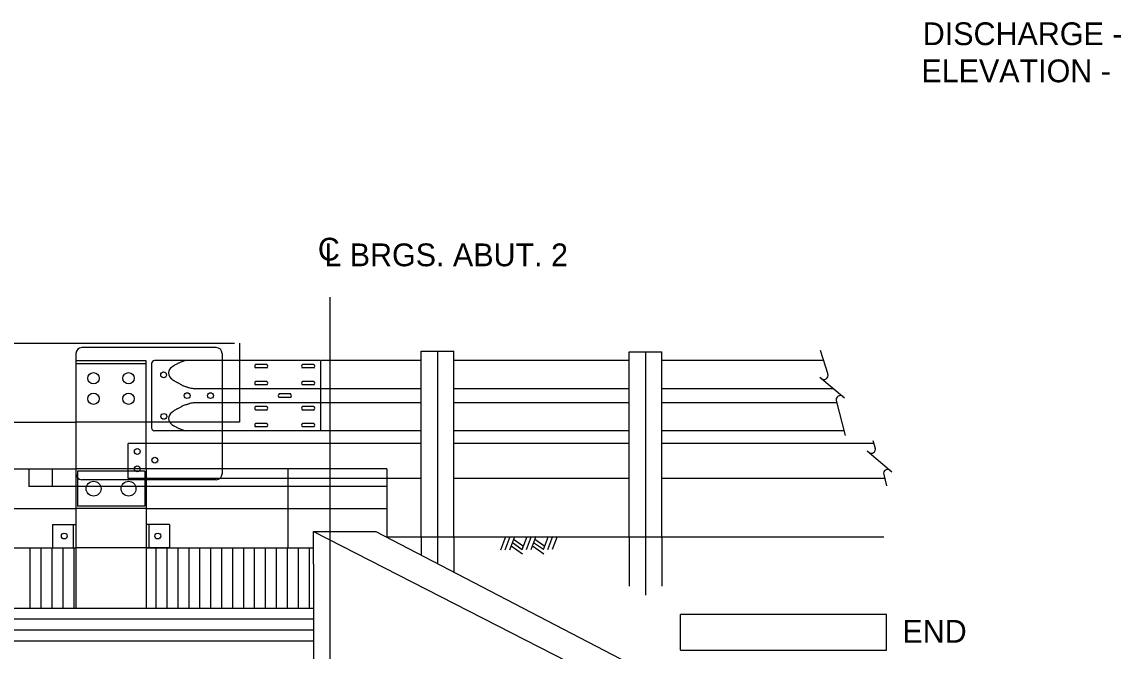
# Model space of a CAD drawing. Extents: x 638263 to 640391, y 293683 to 298655.
# Drawn here: x 638728.4 to 638873.2, y 297468.7 to 297551.6 of the extents above; entities that cross this region are included whole.
import ezdxf

# ---------------------------------------------------------------- set-up
doc = ezdxf.new("R2010")
doc.units = 0
for name, color, linetype in [('2', 7, 'Continuous'), ('3', 7, 'Continuous'), ('4', 7, 'Continuous'), ('5', 7, 'Continuous'), ('Level 25', 7, 'Continuous')]:
    doc.layers.add(name, color=color, linetype=linetype)

msp = doc.modelspace()

# ---------------------------------------------------------------- linework, layer by layer
at = {"layer": '2'}
for p, q in [((638583.44, 297509.28), (638756.44, 297509.28)), ((638757.09, 297509.28), (638757.09, 297506.97)), ((638744.78, 297506.96), (638735.54, 297506.96)), ((638735.54, 297506.96), (638735.54, 297492.72)), ((638744.78, 297506.58), (638735.54, 297506.58)), ((638744.78, 297492.72), (638744.78, 297506.96)), ((638745.51, 297506.61), (638745.51, 297498.11)), ((638757.09, 297506.98), (638745.88, 297506.98)), ((638767.68, 297506.98), (638757.09, 297506.98)), ((638757.09, 297506.96), (638757.09, 297498.88)), ((638767.75, 297506.98), (638767.75, 297497.74)), ((638781.02, 297506.98), (638767.75, 297506.98)), ((638808.42, 297506.98), (638785.35, 297506.98)), ((638834.04, 297506.98), (638812.74, 297506.98)), ((638760.7, 297506.47), (638759.22, 297506.47)), ((638760.7, 297506.01), (638759.22, 297506.01)), ((638766.88, 297506.47), (638765.4, 297506.47)), ((638766.88, 297506.01), (638765.4, 297506.01)), ((638760.7, 297504.25), (638759.22, 297504.25)), ((638760.7, 297503.79), (638759.22, 297503.79)), ((638766.88, 297504.25), (638765.4, 297504.25)), ((638766.88, 297503.79), (638765.4, 297503.79)), ((638757.09, 297503.28), (638751.34, 297503.28)), ((638781.02, 297503.28), (638757.09, 297503.28)), ((638763.79, 297502.59), (638762.32, 297502.59)), ((638808.42, 297503.28), (638785.35, 297503.28)), ((638835.36, 297503.28), (638812.74, 297503.28)), ((638757.09, 297501.43), (638751.34, 297501.43)), ((638781.02, 297501.43), (638757.09, 297501.43)), ((638760.7, 297500.93), (638759.22, 297500.93)), ((638763.79, 297502.13), (638762.32, 297502.13)), ((638766.88, 297500.93), (638765.4, 297500.93)), ((638808.42, 297501.43), (638785.35, 297501.43)), ((638835.8, 297501.43), (638812.74, 297501.43)), ((638760.7, 297500.46), (638759.22, 297500.46)), ((638766.88, 297500.46), (638765.4, 297500.46)), ((638695.15, 297498.88), (638735.54, 297498.88)), ((638744.78, 297498.88), (638735.54, 297498.88)), ((638754.78, 297498.88), (638744.78, 297498.88)), ((638757.09, 297498.88), (638754.78, 297498.88)), ((638760.7, 297498.71), (638759.22, 297498.71)), ((638760.7, 297498.25), (638759.22, 297498.25)), ((638766.88, 297498.71), (638765.4, 297498.71)), ((638766.88, 297498.25), (638765.4, 297498.25)), ((638754.79, 297497.74), (638745.88, 297497.74)), ((638781.02, 297497.74), (638754.79, 297497.74)), ((638808.42, 297497.74), (638785.35, 297497.74)), ((638836.72, 297497.74), (638812.74, 297497.74)), ((638742.43, 297491.46), (638742.43, 297496.08)), ((638754.79, 297496.08), (638742.43, 297496.08)), ((638781.02, 297496.08), (638754.79, 297496.08)), ((638808.42, 297496.08), (638785.35, 297496.08)), ((638840.66, 297496.08), (638812.74, 297496.08)), ((638695.15, 297492.72), (638735.54, 297492.72)), ((638729.37, 297490.41), (638729.37, 297492.72)), ((638732.46, 297490.41), (638732.46, 297492.72)), ((638744.78, 297492.72), (638735.54, 297492.72)), ((638735.54, 297492.72), (638735.54, 297474.4)), ((638744.61, 297492.44), (638735.73, 297492.44)), ((638735.73, 297492.44), (638735.73, 297487.82)), ((638744.61, 297492.44), (638744.61, 297487.82)), ((638776.52, 297492.72), (638744.78, 297492.72)), ((638744.78, 297492.72), (638744.78, 297474.4)), ((638754.79, 297492.72), (638754.79, 297492.06)), ((638776.51, 297491.46), (638742.41, 297491.46)), ((638781.02, 297491.46), (638776.52, 297491.46)), ((638808.42, 297491.46), (638785.35, 297491.46)), ((638842.1, 297491.46), (638812.74, 297491.46)), ((638776.51, 297490.41), (638729.35, 297490.41)), ((638744.61, 297487.82), (638735.73, 297487.82)), ((638695.15, 297487.52), (638735.54, 297487.52)), ((638744.78, 297487.52), (638735.54, 297487.52)), ((638732.45, 297485.42), (638735.54, 297485.42)), ((638732.45, 297485.42), (638732.45, 297482.33)), ((638735.18, 297485.42), (638735.18, 297482.33)), ((638735.54, 297485.42), (638735.54, 297482.33)), ((638747.87, 297485.42), (638744.78, 297485.42)), ((638744.78, 297485.42), (638744.78, 297482.33)), ((638745.14, 297485.42), (638745.14, 297482.33)), ((638747.87, 297485.42), (638747.87, 297482.33)), ((638732.45, 297482.33), (638735.54, 297482.33)), ((638744.78, 297482.33), (638735.54, 297482.33)), ((638747.87, 297482.33), (638744.78, 297482.33))]:
    msp.add_line(p, q, dxfattribs=at)
for centre, radius in [((638737.85, 297504.66), 0.748), ((638742.47, 297504.66), 0.748), ((638747.09, 297505.1), 0.385), ((638737.85, 297501.96), 0.748), ((638742.47, 297501.96), 0.748), ((638750.19, 297502.37), 0.385), ((638753.27, 297502.37), 0.385), ((638747.12, 297499.64), 0.385), ((638743.62, 297495.02), 0.385), ((638745.93, 297493.87), 0.385), ((638743.62, 297492.72), 0.385), ((638737.86, 297490.12), 0.978), ((638742.47, 297490.12), 0.978), ((638734, 297483.88), 0.385), ((638746.32, 297483.88), 0.385)]:
    msp.add_circle(centre, radius, dxfattribs=at)
for centre, radius, start, end in [((638745.88, 297506.61), 0.369, 90, 180), ((638763.15, 297478.14), 31.8, 116.5749, 117.3798), ((638750.01, 297504.42), 2.42, 113.6547, 116.5749), ((638751.42, 297501.2), 5.93, 112.3149, 113.6547), ((638773.74, 297446.81), 64.73, 111.9093, 112.3149), ((638750.29, 297505.11), 1.88, 108.4934, 111.9093), ((638752.92, 297497.25), 10.17, 107.0234, 108.4934), ((638748.65, 297505.35), 0.916, 120.3532, 238.6149), ((638750.97, 297502.7), 4.42, 125.3229, 129.0151), ((638748.97, 297505.53), 0.955, 117.3798, 125.3229), ((638759.36, 297506.24), 0.269, 120.8559, 239.1441), ((638760.56, 297506.24), 0.269, 300.8559, 59.1441), ((638765.54, 297506.24), 0.269, 120.8559, 239.1441), ((638766.74, 297506.24), 0.269, 300.8559, 59.1441), ((638751.4, 297508.3), 4.94, 229.2007, 233.1182), ((638749.09, 297505.22), 1.09, 233.1182, 241.475), ((638936.16, 297849.41), 392.83, 241.475, 241.5275), ((638688.64, 297393.02), 126.36, 61.435, 61.5275), ((638694.04, 297402.92), 115.08, 61.2499, 61.435), ((638759.71, 297522.63), 21.45, 241.2499, 241.6785), ((638749.84, 297504.31), 0.644, 241.6785, 249.7671), ((638755.9, 297520.76), 18.18, 249.7671, 251.2889), ((638759.36, 297504.02), 0.269, 120.8559, 239.1441), ((638760.56, 297504.02), 0.269, 300.8559, 59.1441), ((638765.54, 297504.02), 0.269, 120.8559, 239.1441), ((638766.74, 297504.02), 0.269, 300.8559, 59.1441), ((638751.08, 297506.52), 3.14, 251.2889, 252.6389), ((638777.58, 297591.29), 91.96, 252.6389, 252.8885), ((638751.16, 297505.47), 2.16, 252.8885, 261.633), ((638751.58, 297508.31), 5.03, 261.633, 267.3571), ((638762.46, 297502.36), 0.269, 120.8559, 239.1441), ((638763.66, 297502.36), 0.269, 300.8559, 59.1441), ((638694.04, 297601.79), 115.08, 298.565, 298.7501), ((638759.71, 297482.09), 21.45, 118.3215, 118.7501), ((638749.84, 297500.41), 0.644, 110.2329, 118.3215), ((638755.9, 297483.96), 18.18, 108.7111, 110.2329), ((638751.08, 297498.19), 3.14, 107.3611, 108.7111), ((638777.58, 297413.42), 91.96, 107.1115, 107.3611), ((638751.16, 297499.25), 2.16, 98.367, 107.1115), ((638751.58, 297496.41), 5.03, 92.6429, 98.367), ((638759.36, 297500.7), 0.269, 120.8559, 239.1441), ((638760.56, 297500.7), 0.269, 300.8559, 59.1441), ((638765.54, 297500.7), 0.269, 120.8559, 239.1441), ((638766.74, 297500.7), 0.269, 300.8559, 59.1441), ((638748.65, 297499.37), 0.916, 121.3851, 239.6468), ((638751.4, 297496.41), 4.94, 126.8818, 130.7993), ((638749.09, 297499.49), 1.09, 118.525, 126.8818), ((638936.16, 297155.3), 392.83, 118.4725, 118.525), ((638688.64, 297611.7), 126.36, 298.4725, 298.565), ((638745.88, 297498.11), 0.369, 180, 270), ((638750.97, 297502.01), 4.42, 230.9849, 234.6771), ((638748.97, 297499.19), 0.955, 234.6771, 242.6202), ((638763.15, 297526.58), 31.8, 242.6202, 243.4251), ((638750.01, 297500.3), 2.42, 243.4251, 246.3453), ((638751.42, 297503.52), 5.93, 246.3453, 247.6851), ((638773.74, 297557.91), 64.73, 247.6851, 248.0907), ((638759.36, 297498.48), 0.269, 120.8559, 239.1441), ((638760.56, 297498.48), 0.269, 300.8559, 59.1441), ((638765.54, 297498.48), 0.269, 120.8559, 239.1441), ((638766.74, 297498.48), 0.269, 300.8559, 59.1441), ((638750.29, 297499.61), 1.88, 248.0907, 251.5066), ((638752.92, 297507.46), 10.17, 251.5066, 252.9766)]:
    msp.add_arc(centre, radius, start, end, dxfattribs=at)
at = {"layer": '3'}
for p, q in [((638781.02, 297508.24), (638785.35, 297508.24)), ((638781.02, 297483.77), (638781.02, 297508.24)), ((638783.18, 297508.24), (638783.18, 297480.27)), ((638785.35, 297483.77), (638785.35, 297508.24)), ((638808.42, 297508.16), (638812.74, 297508.16)), ((638808.42, 297483.77), (638808.42, 297508.16)), ((638810.58, 297508.16), (638810.58, 297476.08)), ((638812.74, 297483.77), (638812.74, 297508.16)), ((638833.6, 297508.34), (638834.61, 297505.19)), ((638833.54, 297504.8), (638836.81, 297502.06)), ((638835.73, 297501.72), (638836.88, 297497.13)), ((638840.53, 297496.46), (638840.85, 297495.47)), ((638839.78, 297495.08), (638843.05, 297492.34)), ((638763.51, 297482.33), (638763.51, 297492.72)), ((638776.52, 297492.72), (638776.52, 297483.77)), ((638841.97, 297492), (638842.34, 297490.49)), ((638744.76, 297487.52), (638776.52, 297487.52)), ((638766.86, 297484.49), (638833.06, 297450.61)), ((638766.86, 297484.49), (638775.07, 297484.49)), ((638766.86, 297480.17), (638766.86, 297484.49)), ((638775.07, 297484.49), (638840.19, 297450.61)), ((638776.45, 297483.77), (638842, 297483.77)), ((638781.02, 297483.77), (638781.02, 297481.4)), ((638785.35, 297483.77), (638785.35, 297479.15)), ((638792.15, 297483.77), (638791.48, 297482.02)), ((638792.69, 297483.78), (638792.03, 297482.02)), ((638793.33, 297483.79), (638792.67, 297482.03)), ((638793.2, 297483.45), (638794.49, 297482.55)), ((638794.96, 297483.79), (638794.3, 297482.06)), ((638795.51, 297483.8), (638794.85, 297482.07)), ((638796.14, 297483.8), (638795.49, 297482.08)), ((638796.01, 297483.46), (638797.3, 297482.56)), ((638797.77, 297483.8), (638797.11, 297482.07)), ((638798.32, 297483.81), (638797.66, 297482.08)), ((638798.95, 297483.81), (638798.3, 297482.09)), ((638808.42, 297483.77), (638808.42, 297477.28)), ((638812.74, 297483.77), (638812.74, 297477.28)), ((638695.15, 297482.33), (638735.54, 297482.33)), ((638744.78, 297482.33), (638766.86, 297482.33)), ((638792.87, 297482.57), (638794.37, 297481.53)), ((638793.04, 297483.02), (638794.33, 297482.12)), ((638795.68, 297482.58), (638797.18, 297481.54)), ((638795.85, 297483.03), (638797.14, 297482.13)), ((638766.86, 297480.17), (638766.86, 297418.67)), ((638574.49, 297474.4), (638766.86, 297474.4))]:
    msp.add_line(p, q, dxfattribs=at)
for centre, start, end in [((638834.11, 297505.03), 227.8504, 17.8504), ((638836.25, 297501.84), 49.9832, 192.5218), ((638836.25, 297501.84), 49.9832, 49.9972), ((638840.35, 297495.31), 227.8504, 17.8504), ((638842.49, 297492.12), 49.9832, 192.5218), ((638842.49, 297492.12), 49.9832, 49.9972)]:
    msp.add_arc(centre, 0.533, start, end, dxfattribs=at)
at = {"layer": '4'}
for p, q in [((638769.01, 297515.36), (638769.01, 297449.75)), ((638842.34, 297473.55), (638815.19, 297473.55)), ((638815.19, 297468.85), (638815.19, 297473.55)), ((638842.34, 297468.85), (638842.34, 297473.55)), ((638815.19, 297468.85), (638842.34, 297468.85))]:
    msp.add_line(p, q, dxfattribs=at)
at = {"layer": '5'}
for p, q in [((638729.48, 297482.33), (638729.48, 297474.4)), ((638730.93, 297482.33), (638730.93, 297474.4)), ((638732.37, 297482.33), (638732.37, 297474.4)), ((638733.82, 297482.33), (638733.82, 297474.4)), ((638735.26, 297482.33), (638735.26, 297474.4)), ((638746.07, 297482.33), (638746.07, 297474.4)), ((638747.51, 297482.33), (638747.51, 297474.4)), ((638748.95, 297482.33), (638748.95, 297474.4)), ((638750.39, 297482.33), (638750.39, 297474.4)), ((638751.83, 297482.33), (638751.83, 297474.4)), ((638753.28, 297482.33), (638753.28, 297474.4)), ((638754.72, 297482.33), (638754.72, 297474.4)), ((638756.16, 297482.33), (638756.16, 297474.4)), ((638757.6, 297482.33), (638757.6, 297474.4)), ((638759.04, 297482.33), (638759.04, 297474.4)), ((638760.48, 297482.33), (638760.48, 297474.4)), ((638761.93, 297482.33), (638761.93, 297474.4)), ((638763.37, 297482.33), (638763.37, 297474.4)), ((638764.81, 297482.33), (638764.81, 297474.4)), ((638766.25, 297482.33), (638766.25, 297474.4)), ((638574.49, 297472.96), (638766.86, 297472.96)), ((638574.49, 297471.52), (638766.86, 297471.52)), ((638574.49, 297470.07), (638766.86, 297470.07))]:
    msp.add_line(p, q, dxfattribs=at)
at = {"layer": 'Level 25'}
for p, q in [((638754.02, 297508.7), (638736.31, 297508.7)), ((638735.54, 297507.93), (638735.54, 297506.96)), ((638754.79, 297507.93), (638754.79, 297506.97)), ((638754.79, 297506.97), (638754.79, 297497.73)), ((638754.79, 297497.73), (638754.79, 297492.72)), ((638754.02, 297491.29), (638736.31, 297491.29))]:
    msp.add_line(p, q, dxfattribs=at)
for centre, start, end in [((638736.31, 297507.93), 90, 180), ((638754.02, 297507.93), 0, 90), ((638736.31, 297492.06), 180, 270), ((638754.02, 297492.06), 270, 0)]:
    msp.add_arc(centre, 0.77, start, end, dxfattribs=at)

# ---------------------------------------------------------------- texts
at = {"layer": '4'}
for s, p in [('   DISCHARGE - ', (638843.78, 297548.53)), ('   ELEVATION - ', (638843.6, 297543.64)), ('C', (638767.41, 297520.16)), ('L BRGS. ABUT. 2', (638768.27, 297519.41)), ('END', (638844.44, 297469.83))]:
    msp.add_text(s, height=3, dxfattribs=at).set_placement(p)

doc.saveas('drawing.dxf')
